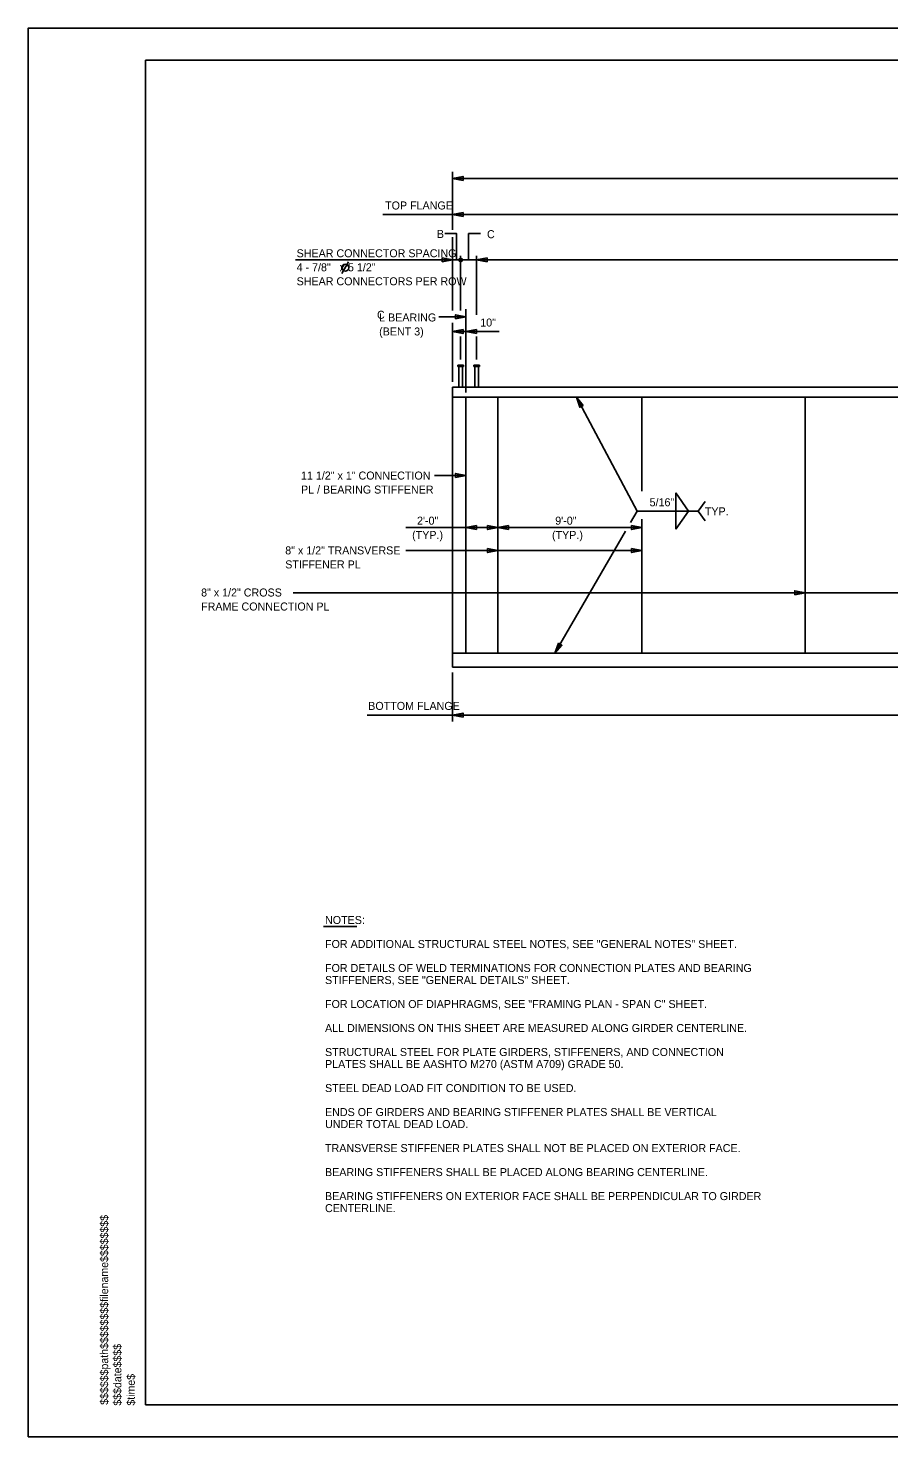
# Model space of a CAD drawing. Extents: x -383 to -161, y -356 to -99.
# Drawn here: x -305.2 to -251.4, y -187.5 to -99.5 of the extents above; entities that cross this region are included whole.
import ezdxf

# ---------------------------------------------------------------- set-up
doc = ezdxf.new("R2010")
doc.units = 0
for name, color, linetype in [('BR_AUTO DIMENSION', 7, 'Continuous'), ('BR_BORDER LINES', 7, 'Continuous'), ('BR_CENTER LINES', 7, 'Continuous'), ('BR_STRUCTURAL STEEL', 7, 'Continuous'), ('BR_TEXT', 7, 'Continuous'), ('Default', 7, 'Continuous'), ('Level 31', 7, 'Continuous'), ('RD_SHT_ID', 7, 'Continuous')]:
    doc.layers.add(name, color=color, linetype=linetype)

msp = doc.modelspace()

# ---------------------------------------------------------------- linework, layer by layer
at = {"layer": 'BR_AUTO DIMENSION'}
for p, q in [((-278.644, -112.097), (-278.644, -108.463)), ((-278.644, -108.876), (-183.048, -108.876)), ((-278.644, -111.134), (-283.014, -111.134)), ((-278.644, -111.134), (-183.048, -111.134)), ((-278.644, -117.118), (-278.644, -112.544)), ((-278.644, -113.971), (-288.461, -113.971)), ((-277.144, -113.971), (-278.644, -113.971)), ((-278.144, -117.118), (-278.144, -113.71)), ((-277.144, -117.407), (-277.144, -113.71)), ((-184.548, -113.971), (-277.144, -113.971)), ((-277.811, -117.522), (-279.513, -117.522)), ((-278.644, -121.593), (-278.644, -117.889)), ((-278.644, -118.446), (-275.73, -118.446)), ((-278.144, -120.185), (-278.144, -118.756)), ((-277.144, -120.185), (-277.144, -118.756)), ((-267.121, -129.657), (-270.897, -122.537)), ((-277.811, -127.431), (-279.776, -127.431)), ((-264.706, -128.523), (-264.706, -130.791)), ((-264.706, -128.523), (-263.9, -129.657)), ((-263.297, -129.657), (-262.864, -129.05)), ((-267.121, -129.657), (-267.533, -130.37)), ((-267.121, -129.657), (-263.297, -129.657)), ((-264.706, -130.791), (-263.9, -129.657)), ((-263.297, -129.657), (-262.864, -130.264)), ((-275.811, -130.686), (-281.569, -130.686)), ((-266.811, -130.686), (-275.811, -130.686)), ((-267.844, -130.909), (-272.251, -138.537)), ((-266.811, -132.128), (-281.569, -132.128)), ((-205.077, -134.756), (-288.61, -134.756)), ((-278.644, -139.746), (-278.644, -142.798)), ((-278.644, -142.397), (-283.992, -142.397)), ((-278.644, -142.397), (-183.048, -142.397)), ((-286.712, -155.612), (-284.636, -155.612))]:
    msp.add_line(p, q, dxfattribs=at)
for points in [[(-277.994, -109.001), (-278.644, -108.876), (-277.994, -108.751)], [(-277.994, -111.259), (-278.644, -111.134), (-277.994, -111.009)], [(-279.294, -114.096), (-278.644, -113.971), (-279.294, -113.846)], [(-276.494, -114.096), (-277.144, -113.971), (-276.494, -113.846)], [(-278.461, -117.647), (-277.811, -117.522), (-278.461, -117.397)], [(-277.994, -118.321), (-278.644, -118.446), (-277.994, -118.571)], [(-277.161, -118.571), (-277.811, -118.446), (-277.161, -118.321)], [(-270.482, -123.053), (-270.897, -122.537), (-270.703, -123.17)], [(-278.461, -127.556), (-277.811, -127.431), (-278.461, -127.306)], [(-277.161, -130.811), (-277.811, -130.686), (-277.161, -130.561)], [(-276.461, -130.561), (-275.811, -130.686), (-276.461, -130.811)], [(-275.161, -130.811), (-275.811, -130.686), (-275.161, -130.561)], [(-267.461, -130.561), (-266.811, -130.686), (-267.461, -130.811)], [(-276.461, -132.003), (-275.811, -132.128), (-276.461, -132.253)], [(-267.461, -132.003), (-266.811, -132.128), (-267.461, -132.253)], [(-257.265, -134.881), (-256.615, -134.756), (-257.265, -134.631)], [(-272.034, -137.912), (-272.251, -138.537), (-271.818, -138.037)], [(-277.994, -142.522), (-278.644, -142.397), (-277.994, -142.272)]]:
    msp.add_lwpolyline(points, close=True, dxfattribs=at)
for points in [[(-278.394, -113.971), (-278.394, -112.325), (-279.134, -112.325)], [(-277.644, -113.971), (-277.644, -112.325), (-276.904, -112.325)]]:
    msp.add_lwpolyline(points, dxfattribs=at)
msp.add_circle((-278.144, -113.971), 0.111, dxfattribs=at)
at = {"layer": 'BR_BORDER LINES'}
for p, q in [((-163.178, -101.489), (-297.843, -101.489)), ((-297.843, -185.489), (-297.843, -101.489)), ((-297.843, -185.489), (-163.178, -185.489))]:
    msp.add_line(p, q, dxfattribs=at)
at = {"layer": 'BR_CENTER LINES'}
msp.add_line((-277.811, -117.035), (-277.811, -122.256), dxfattribs=at)
at = {"layer": 'BR_STRUCTURAL STEEL'}
for p, q in [((-278.644, -122.537), (-278.644, -121.912)), ((-278.644, -121.912), (-183.048, -121.912)), ((-278.644, -122.537), (-183.048, -122.537)), ((-278.644, -122.537), (-278.644, -138.537)), ((-277.811, -122.537), (-277.811, -138.537)), ((-275.811, -122.537), (-275.811, -138.537)), ((-266.811, -122.537), (-266.811, -128.423)), ((-256.615, -122.537), (-256.615, -138.537)), ((-266.811, -130.152), (-266.811, -138.537)), ((-278.644, -138.537), (-183.048, -138.537)), ((-278.644, -138.537), (-278.644, -139.412)), ((-278.644, -139.412), (-183.048, -139.412))]:
    msp.add_line(p, q, dxfattribs=at)
at = {"layer": 'BR_TEXT'}
msp.add_line((-285.568, -114.817), (-285.148, -114.089), dxfattribs=at)
msp.add_circle((-285.358, -114.453), 0.22, dxfattribs=at)
at = {"layer": 'Default'}
for p, q in [((-278.316, -120.537), (-278.316, -120.631)), ((-278.316, -120.537), (-277.972, -120.537)), ((-277.972, -120.537), (-277.972, -120.631)), ((-277.316, -120.537), (-277.316, -120.631)), ((-277.316, -120.537), (-276.972, -120.537)), ((-276.972, -120.537), (-276.972, -120.631)), ((-278.316, -120.631), (-277.972, -120.631)), ((-278.253, -120.631), (-278.253, -121.912)), ((-278.035, -120.631), (-278.035, -121.912)), ((-277.316, -120.631), (-276.972, -120.631)), ((-277.253, -120.631), (-277.253, -121.912)), ((-277.035, -120.631), (-277.035, -121.912))]:
    msp.add_line(p, q, dxfattribs=at)
at = {"layer": 'Level 31'}
msp.add_lwpolyline([(-305.176, -187.489), (-161.176, -187.489), (-161.176, -99.489), (-305.176, -99.489)], close=True, dxfattribs=at)

# ---------------------------------------------------------------- texts
at = {"layer": 'BR_AUTO DIMENSION'}
for s, p in [('TOP FLANGE', (-282.866, -110.815)), ('B', (-279.63, -112.593)), ('C', (-276.497, -112.609)), ('10"', (-276.92, -118.127)), ('5/16"', (-266.334, -129.357)), ('2\'-0"', (-280.872, -130.507)), ('9\'-0"', (-272.234, -130.507)), ('TYP.', (-262.88, -129.923)), ('(TYP.)', (-281.177, -131.398)), ('(TYP.)', (-272.434, -131.398)), ('BOTTOM FLANGE', (-283.92, -142.078)), ('NOTES:', (-286.621, -155.451)), ('FOR ADDITIONAL STRUCTURAL STEEL NOTES, SEE "GENERAL NOTES" SHEET.', (-286.621, -156.951)), ('FOR DETAILS OF WELD TERMINATIONS FOR CONNECTION PLATES AND BEARING ', (-286.621, -158.451)), ('STIFFENERS, SEE "GENERAL DETAILS" SHEET.', (-286.621, -159.201)), ('FOR LOCATION OF DIAPHRAGMS, SEE "FRAMING PLAN - SPAN C" SHEET.', (-286.621, -160.701)), ('ALL DIMENSIONS ON THIS SHEET ARE MEASURED ALONG GIRDER CENTERLINE.', (-286.621, -162.201)), ('STRUCTURAL STEEL FOR PLATE GIRDERS, STIFFENERS, AND CONNECTION ', (-286.621, -163.701)), ('PLATES SHALL BE AASHTO M270 (ASTM A709) GRADE 50.', (-286.621, -164.451)), ('STEEL DEAD LOAD FIT CONDITION TO BE USED.', (-286.621, -165.951)), ('ENDS OF GIRDERS AND BEARING STIFFENER PLATES SHALL BE VERTICAL', (-286.621, -167.451)), ('UNDER TOTAL DEAD LOAD.', (-286.621, -168.201)), ('TRANSVERSE STIFFENER PLATES SHALL NOT BE PLACED ON EXTERIOR FACE.', (-286.621, -169.701)), ('BEARING STIFFENERS SHALL BE PLACED ALONG BEARING CENTERLINE.', (-286.621, -171.201)), ('BEARING STIFFENERS ON EXTERIOR FACE SHALL BE PERPENDICULAR TO GIRDER', (-286.621, -172.701)), ('CENTERLINE.', (-286.621, -173.451))]:
    msp.add_text(s, height=0.5, rotation=360, dxfattribs=at).set_placement(p)
at = {"layer": 'BR_TEXT'}
for s, p in [('SHEAR CONNECTOR SPACING', (-288.397, -113.801)), ('4 - 7/8"   x 5 1/2" ', (-288.397, -114.676)), ('SHEAR CONNECTORS PER ROW', (-288.397, -115.551)), ('C', (-283.374, -117.645)), ('L BEARING', (-283.239, -117.811)), ('(BENT 3)', (-283.239, -118.686)), ('11 1/2" x 1" CONNECTION ', (-288.123, -127.688)), ('PL / BEARING STIFFENER', (-288.123, -128.563)), ('8" x 1/2" TRANSVERSE ', (-289.108, -132.364)), ('STIFFENER PL', (-289.108, -133.239)), ('8" x 1/2" CROSS ', (-294.367, -134.993)), ('FRAME CONNECTION PL', (-294.367, -135.868))]:
    msp.add_text(s, height=0.5, rotation=360, dxfattribs=at).set_placement(p)
at = {"layer": 'RD_SHT_ID'}
for s, height, p in [('$$$$$$path$$$$$$$$filename$$$$$$$$', 0.49387, (-300.176, -185.489)), ('$$$date$$$$', 0.49387, (-299.353, -185.542)), ('$time$', 0.4939, (-298.509, -185.542))]:
    msp.add_text(s, height=height, rotation=90, dxfattribs=at).set_placement(p)

doc.saveas('drawing.dxf')
